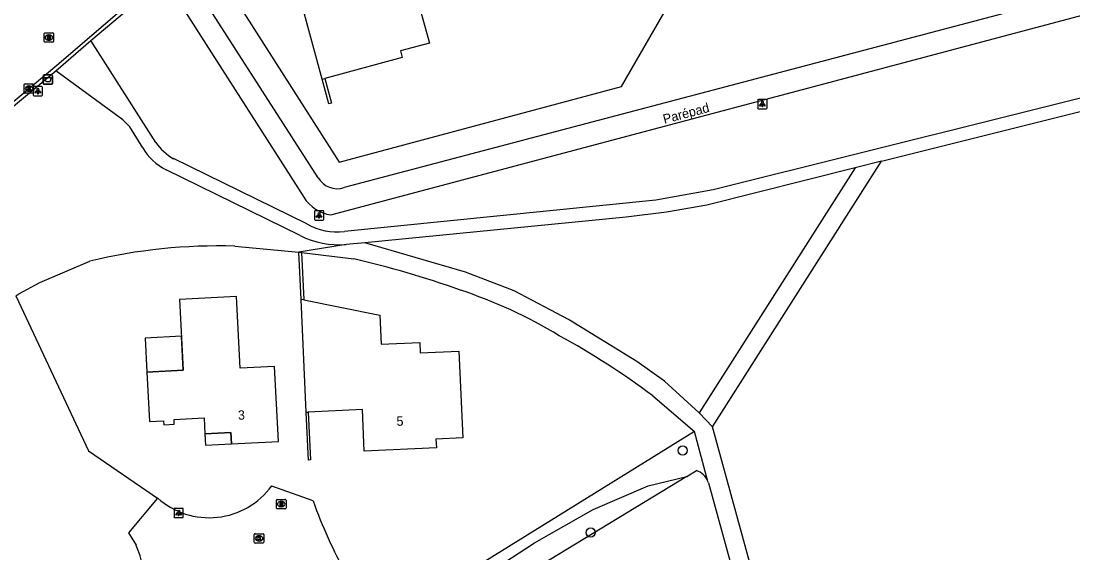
# Model space of a CAD drawing. Extents: x 162157 to 163165, y 378998 to 380775.
# Drawn here: x 162684.3 to 162796.7, y 380157.8 to 380214.6 of the extents above; entities that cross this region are included whole.
import ezdxf

# ---------------------------------------------------------------- set-up
doc = ezdxf.new("R2010")
doc.units = 0
for name, color, linetype in [('IMGEO_Afvalbak', 7, 'Continuous'), ('IMGEO_Boom', 7, 'Continuous'), ('IMGEO_Gemengd_bos', 7, 'Continuous'), ('IMGEO_Grasland_overig', 7, 'Continuous'), ('IMGEO_Groenvoorziening', 7, 'Continuous'), ('IMGEO_Kolk', 7, 'Continuous'), ('IMGEO_Lichtpunt', 7, 'Continuous'), ('IMGEO_Muur', 7, 'Continuous'), ('IMGEO_Naaldbos', 7, 'Continuous'), ('IMGEO_Openbare_ruimte_label', 7, 'Continuous'), ('IMGEO_Pand', 7, 'Continuous'), ('IMGEO_Pand_nummerreeks', 7, 'Continuous'), ('IMGEO_Pand_overbouw', 7, 'Continuous'), ('IMGEO_Rijbaan_lokaal_gesloten', 7, 'Continuous'), ('IMGEO_Rijbaan_lokaal_open', 7, 'Continuous'), ('IMGEO_Rioolput', 7, 'Continuous'), ('IMGEO_Voetpad_halfverhard', 7, 'Continuous'), ('IMGEO_Voetpad_open', 7, 'Continuous')]:
    doc.layers.add(name, color=color, linetype=linetype)

msp = doc.modelspace()

# ---------------------------------------------------------------- linework, layer by layer
at = {"layer": 'IMGEO_Afvalbak'}
for p, q in [((162686.68, 380207.92), (162686.68, 380208.72)), ((162686.68, 380208.72), (162686.68, 380207.92)), ((162686.78, 380208.82), (162687.57, 380208.82)), ((162687.57, 380208.82), (162686.78, 380208.82)), ((162687.67, 380208.72), (162687.67, 380207.92)), ((162687.67, 380207.92), (162687.67, 380208.72)), ((162687.57, 380207.82), (162686.78, 380207.82)), ((162686.78, 380207.82), (162687.57, 380207.82))]:
    msp.add_line(p, q, dxfattribs=at)
msp.add_lwpolyline([(162686.82, 380208.54), (162687.53, 380208.54), (162687.38, 380208.07), (162686.97, 380208.07), (162686.82, 380208.54)], dxfattribs=at)
for centre, start, end in [((162686.78, 380208.72), 90, 180), ((162686.78, 380208.72), 90, 180), ((162687.57, 380208.72), 0, 90), ((162687.57, 380208.72), 360, 90), ((162686.78, 380207.92), 180, 270), ((162686.78, 380207.92), 180, 270), ((162687.57, 380207.92), 270, 0), ((162687.57, 380207.92), 270, 0)]:
    msp.add_arc(centre, 0.1, start, end, dxfattribs=at)
at = {"layer": 'IMGEO_Boom'}
for centre in [(162755.02, 380168.72), (162745.18, 380159.96)]:
    msp.add_circle(centre, 0.489, dxfattribs=at)
at = {"layer": 'IMGEO_Gemengd_bos'}
msp.add_lwpolyline([(162706.23, 380218.45), (162718.29, 380199.51), (162748.49, 380207.59), (162771.73, 380247.86), (162783, 380245.41)], dxfattribs=at)
at = {"layer": 'IMGEO_Grasland_overig'}
msp.add_lwpolyline([(162683.75, 380185.24), (162691.52, 380168.67), (162698.9, 380163.63)], dxfattribs=at)
at = {"layer": 'IMGEO_Groenvoorziening'}
msp.add_lwpolyline([(162755.47, 380165.95), (162726.2, 380148.17)], dxfattribs=at)
at = {"layer": 'IMGEO_Kolk'}
for p, q in [((162684.65, 380206.94), (162684.65, 380207.79)), ((162684.73, 380207.87), (162685.58, 380207.87)), ((162685.14, 380207.64), (162685.17, 380207.64)), ((162685.65, 380207.79), (162685.65, 380206.94)), ((162685.58, 380206.86), (162684.73, 380206.86)), ((162685.16, 380207.09), (162685.14, 380207.09)), ((162709.23, 380158.91), (162709.23, 380159.76)), ((162709.31, 380159.83), (162710.16, 380159.83)), ((162709.72, 380159.61), (162709.75, 380159.61)), ((162710.24, 380159.76), (162710.24, 380158.91)), ((162710.16, 380158.83), (162709.31, 380158.83)), ((162709.74, 380159.05), (162709.72, 380159.05))]:
    msp.add_line(p, q, dxfattribs=at)
for points in [[(162684.65, 380206.94), (162684.65, 380207.79)], [(162684.73, 380207.87), (162685.58, 380207.87)], [(162685.65, 380207.79), (162685.65, 380206.94)], [(162685.58, 380206.86), (162684.73, 380206.86)], [(162684.97, 380207.56), (162685.1, 380207.56), (162685.1, 380207.41), (162685.23, 380207.56), (162685.39, 380207.56), (162685.25, 380207.41), (162685.4, 380207.16), (162685.25, 380207.16), (162685.16, 380207.33), (162685.1, 380207.26), (162685.1, 380207.16), (162684.97, 380207.16), (162684.97, 380207.56)], [(162709.23, 380158.91), (162709.23, 380159.76)], [(162709.31, 380159.83), (162710.16, 380159.83)], [(162709.55, 380159.53), (162709.68, 380159.53), (162709.68, 380159.38), (162709.81, 380159.53), (162709.97, 380159.53), (162709.83, 380159.38), (162709.98, 380159.13), (162709.83, 380159.13), (162709.74, 380159.3), (162709.68, 380159.23), (162709.68, 380159.13), (162709.55, 380159.13), (162709.55, 380159.53)], [(162710.24, 380159.76), (162710.24, 380158.91)], [(162710.16, 380158.83), (162709.31, 380158.83)]]:
    msp.add_lwpolyline(points, dxfattribs=at)
for centre, start, end in [((162684.73, 380207.79), 91.552, 178.448), ((162684.73, 380207.79), 91.552, 178.448), ((162685.58, 380207.79), 1.552, 88.448), ((162685.58, 380207.79), 1.552, 88.448), ((162684.73, 380206.94), 181.552, 268.448), ((162684.73, 380206.94), 181.552, 268.448), ((162685.58, 380206.94), 271.552, 358.448), ((162685.58, 380206.94), 271.552, 358.448), ((162709.31, 380159.76), 91.552, 178.448), ((162709.31, 380159.76), 91.552, 178.448), ((162710.16, 380159.76), 1.552, 88.448), ((162710.16, 380159.76), 1.552, 88.448), ((162709.31, 380158.91), 181.552, 268.448), ((162709.31, 380158.91), 181.552, 268.448), ((162710.16, 380158.91), 271.552, 358.448), ((162710.16, 380158.91), 271.552, 358.448)]:
    msp.add_arc(centre, 0.0765, start, end, dxfattribs=at)
for centre, major_axis, ratio, start_param, end_param in [((162685.14, 380207.36), (-0.387, 0.002), 0.722429, 4.712389, 7.853982), ((162685.16, 380207.36), (-0.39, 0.002), 0.717154, 1.570796, 4.712389), ((162709.72, 380159.33), (-0.387, 0.002), 0.722429, 4.712389, 7.853982), ((162709.75, 380159.33), (-0.39, 0.002), 0.717154, 1.570796, 4.712389)]:
    msp.add_ellipse(centre, major_axis=major_axis, ratio=ratio, start_param=start_param, end_param=end_param, dxfattribs=at)
at = {"layer": 'IMGEO_Lichtpunt'}
for p, q in [((162686.51, 380207.58), (162685.71, 380207.58)), ((162686.51, 380207.58), (162685.71, 380207.58)), ((162685.61, 380207.49), (162685.61, 380206.68)), ((162685.61, 380207.49), (162685.61, 380206.68)), ((162685.71, 380206.59), (162686.51, 380206.59)), ((162685.71, 380206.59), (162686.51, 380206.59)), ((162686.61, 380206.68), (162686.61, 380207.49)), ((162686.61, 380206.68), (162686.61, 380207.49)), ((162763.03, 380206.11), (162763.03, 380205.31)), ((162763.03, 380206.11), (162763.03, 380205.31)), ((162763.93, 380206.21), (162763.12, 380206.21)), ((162763.93, 380206.21), (162763.12, 380206.21)), ((162764.03, 380205.31), (162764.03, 380206.11)), ((162764.03, 380205.31), (162764.03, 380206.11)), ((162763.12, 380205.21), (162763.93, 380205.21)), ((162763.12, 380205.21), (162763.93, 380205.21)), ((162715.65, 380194.23), (162715.65, 380193.42)), ((162715.65, 380194.23), (162715.65, 380193.42)), ((162716.55, 380194.32), (162715.75, 380194.32)), ((162716.55, 380194.32), (162715.75, 380194.32)), ((162716.65, 380193.42), (162716.65, 380194.23)), ((162716.65, 380193.42), (162716.65, 380194.23)), ((162715.75, 380193.32), (162716.55, 380193.32)), ((162715.75, 380193.32), (162716.55, 380193.32)), ((162700.65, 380162.45), (162700.65, 380161.64)), ((162700.65, 380162.45), (162700.65, 380161.64)), ((162701.55, 380162.54), (162700.74, 380162.54)), ((162701.55, 380162.54), (162700.74, 380162.54)), ((162700.74, 380161.55), (162701.55, 380161.55)), ((162700.74, 380161.55), (162701.55, 380161.55)), ((162701.64, 380161.64), (162701.64, 380162.45)), ((162701.64, 380161.64), (162701.64, 380162.45))]:
    msp.add_line(p, q, dxfattribs=at)
for points in [[(162685.99, 380207.15), (162686.03, 380207.13), (162685.84, 380206.86), (162685.8, 380206.89), (162685.99, 380207.15)], [(162686.09, 380207.11), (162686.14, 380207.11), (162686.14, 380206.78), (162686.09, 380206.78), (162686.09, 380207.11)], [(162686.2, 380207.13), (162686.24, 380207.15), (162686.42, 380206.89), (162686.39, 380206.86), (162686.2, 380207.13)], [(162763.4, 380205.78), (162763.44, 380205.75), (162763.26, 380205.49), (162763.22, 380205.51), (162763.4, 380205.78)], [(162763.51, 380205.73), (162763.55, 380205.73), (162763.55, 380205.41), (162763.51, 380205.41), (162763.51, 380205.73)], [(162763.62, 380205.75), (162763.65, 380205.78), (162763.84, 380205.51), (162763.8, 380205.49), (162763.62, 380205.75)], [(162716.03, 380193.89), (162716.06, 380193.86), (162715.88, 380193.6), (162715.84, 380193.63), (162716.03, 380193.89)], [(162716.13, 380193.84), (162716.17, 380193.84), (162716.17, 380193.52), (162716.13, 380193.52), (162716.13, 380193.84)], [(162716.24, 380193.86), (162716.28, 380193.89), (162716.46, 380193.63), (162716.42, 380193.6), (162716.24, 380193.86)], [(162701.02, 380162.11), (162701.06, 380162.09), (162700.87, 380161.82), (162700.83, 380161.85), (162701.02, 380162.11)], [(162701.12, 380162.07), (162701.17, 380162.07), (162701.17, 380161.74), (162701.12, 380161.74), (162701.12, 380162.07)], [(162701.23, 380162.09), (162701.27, 380162.11), (162701.46, 380161.85), (162701.42, 380161.82), (162701.23, 380162.09)]]:
    msp.add_lwpolyline(points, dxfattribs=at)
for centre in [(162686.11, 380207.29), (162763.53, 380205.91), (162716.15, 380194.02), (162701.15, 380162.25)]:
    msp.add_circle(centre, 0.0994, dxfattribs=at)
for centre, start, end in [((162685.71, 380207.49), 90, 180), ((162685.71, 380207.49), 90, 180), ((162686.51, 380207.49), 0, 90), ((162686.51, 380207.49), 0, 90), ((162685.71, 380206.68), 180, 270), ((162685.71, 380206.68), 180, 270), ((162686.51, 380206.68), 270, 0), ((162686.51, 380206.68), 270, 360), ((162763.12, 380206.11), 90, 180), ((162763.12, 380206.11), 90, 180), ((162763.93, 380206.11), 0, 90), ((162763.93, 380206.11), 0, 90), ((162763.12, 380205.31), 180, 270), ((162763.12, 380205.31), 180, 270), ((162763.93, 380205.31), 270, 0), ((162763.93, 380205.31), 270, 360), ((162715.75, 380194.23), 90, 180), ((162715.75, 380194.23), 90, 180), ((162716.55, 380194.23), 0, 90), ((162716.55, 380194.23), 0, 90), ((162715.75, 380193.42), 180, 270), ((162715.75, 380193.42), 180, 270), ((162716.55, 380193.42), 270, 0), ((162716.55, 380193.42), 270, 360), ((162700.74, 380162.45), 90, 180), ((162700.74, 380162.45), 90, 180), ((162700.74, 380161.64), 180, 270), ((162700.74, 380161.64), 180, 270), ((162701.55, 380162.45), 0, 90), ((162701.55, 380162.45), 0, 90), ((162701.55, 380161.64), 270, 0), ((162701.55, 380161.64), 270, 360)]:
    msp.add_arc(centre, 0.0946, start, end, dxfattribs=at)
at = {"layer": 'IMGEO_Muur'}
for points in [[(162716.77, 380208.45), (162717.49, 380205.82), (162717.2, 380205.74), (162716.49, 380208.37)], [(162714, 380189.9), (162714.28, 380189.87)], [(162714.23, 380184.85), (162714, 380189.9)], [(162714.28, 380189.87), (162714.52, 380184.79)], [(162715, 380172.81), (162715.23, 380167.71), (162715.03, 380167.7), (162714.79, 380172.8)]]:
    msp.add_lwpolyline(points, dxfattribs=at)
at = {"layer": 'IMGEO_Naaldbos'}
for points in [[(162707.14, 380190.54), (162714, 380189.9)], [(162683.75, 380185.24), (162684.07, 380185.46), (162686.32, 380186.65), (162691.65, 380188.94)]]:
    msp.add_lwpolyline(points, dxfattribs=at)
msp.add_arc((162705.36, 380131.99), 58.57, 88.2597, 103.5364, dxfattribs=at)
at = {"layer": 'IMGEO_Pand'}
for points in [[(162716.49, 380208.37), (162714.39, 380216.1), (162715.1, 380216.3), (162714.03, 380220.25), (162720.57, 380222.02), (162719.45, 380226.13), (162723.68, 380227.27)], [(162723.9, 380227.33), (162727.13, 380215.42), (162727.08, 380215.4), (162727.94, 380212.22), (162724.86, 380211.39), (162725.05, 380210.69), (162716.77, 380208.45)], [(162716.49, 380208.37), (162716.77, 380208.45)], [(162707.33, 380185.16), (162701.24, 380184.84), (162701.63, 380177.28), (162697.75, 380177.08), (162698.03, 380171.82), (162699.54, 380171.9), (162699.56, 380171.47), (162700.68, 380171.52), (162700.65, 380172.02), (162703.87, 380172.19), (162703.96, 380170.51), (162706.74, 380170.65), (162706.8, 380169.43), (162711.82, 380169.69), (162711.4, 380177.68), (162707.73, 380177.49), (162707.33, 380185.16)], [(162714.79, 380172.8), (162714.23, 380184.85)], [(162714.52, 380184.79), (162714.23, 380184.85)], [(162714.52, 380184.79), (162722.65, 380183.18), (162722.8, 380180.07), (162726.92, 380180.26), (162726.97, 380179.15), (162731.08, 380179.34), (162731.51, 380170.08), (162728.64, 380169.94), (162728.69, 380169.01), (162720.99, 380168.66), (162720.79, 380173.08), (162715, 380172.81)], [(162714.79, 380172.8), (162715, 380172.81)]]:
    msp.add_lwpolyline(points, dxfattribs=at)
at = {"layer": 'IMGEO_Pand_overbouw'}
for points in [[(162697.56, 380180.72), (162697.75, 380177.08), (162701.63, 380177.28), (162701.44, 380180.93)], [(162703.96, 380170.51), (162704.02, 380169.28), (162706.8, 380169.43), (162706.74, 380170.65)]]:
    msp.add_lwpolyline(points, close=True, dxfattribs=at)
at = {"layer": 'IMGEO_Rijbaan_lokaal_gesloten'}
msp.add_lwpolyline([(162699.33, 380219.44), (162688.11, 380209.84), (162656.75, 380183.58)], dxfattribs=at)
at = {"layer": 'IMGEO_Rijbaan_lokaal_open'}
for points in [[(162691.75, 380212.48), (162699.59, 380219.12)], [(162688.01, 380209.27), (162691.75, 380212.48)], [(162655.18, 380181.88), (162688.01, 380209.27)], [(162715.51, 380163.34), (162711.09, 380164.92)], [(162698.9, 380163.63), (162695.78, 380159.94), (162696.6, 380158.59)]]:
    msp.add_lwpolyline(points, dxfattribs=at)
for centre, radius, start, end in [((162704.41, 380169.83), 8.29, 228.3998, 323.7405), ((162766.9, 380181.89), 54.64, 199.8527, 208.8663), ((162688.65, 380154.93), 8.75, 353.8956, 24.664)]:
    msp.add_arc(centre, radius, start, end, dxfattribs=at)
at = {"layer": 'IMGEO_Rioolput'}
for p, q in [((162686.78, 380212.39), (162686.78, 380213.24)), ((162686.85, 380213.31), (162687.7, 380213.31)), ((162687.78, 380213.24), (162687.78, 380212.39)), ((162687.7, 380212.31), (162686.85, 380212.31)), ((162687.26, 380213.09), (162687.29, 380213.09)), ((162687.29, 380212.53), (162687.26, 380212.53)), ((162711.62, 380162.57), (162711.62, 380163.42)), ((162711.69, 380163.49), (162712.54, 380163.49)), ((162712.1, 380163.27), (162712.13, 380163.27)), ((162712.13, 380162.71), (162712.1, 380162.71)), ((162712.62, 380163.42), (162712.62, 380162.57)), ((162712.54, 380162.49), (162711.69, 380162.49))]:
    msp.add_line(p, q, dxfattribs=at)
for points in [[(162686.78, 380212.39), (162686.78, 380213.24)], [(162686.85, 380213.31), (162687.7, 380213.31)], [(162687.78, 380213.24), (162687.78, 380212.39)], [(162687.7, 380212.31), (162686.85, 380212.31)], [(162687.36, 380213.01), (162687.11, 380213.01), (162687.11, 380212.61)], [(162687.11, 380212.61), (162687.24, 380212.61), (162687.24, 380212.78), (162687.25, 380212.78)], [(162687.29, 380212.93), (162687.24, 380212.93), (162687.24, 380212.85)], [(162687.24, 380212.85), (162687.29, 380212.85)], [(162687.29, 380212.75), (162687.37, 380212.61), (162687.5, 380212.61), (162687.44, 380212.74)], [(162711.62, 380162.57), (162711.62, 380163.42)], [(162711.69, 380163.49), (162712.54, 380163.49)], [(162712.21, 380163.19), (162711.95, 380163.19), (162711.95, 380162.79)], [(162711.95, 380162.79), (162712.08, 380162.79), (162712.08, 380162.96), (162712.09, 380162.96)], [(162712.13, 380163.11), (162712.08, 380163.11), (162712.08, 380163.03)], [(162712.08, 380163.03), (162712.13, 380163.03)], [(162712.13, 380162.93), (162712.21, 380162.79), (162712.35, 380162.79), (162712.28, 380162.92)], [(162712.62, 380163.42), (162712.62, 380162.57)], [(162712.54, 380162.49), (162711.69, 380162.49)]]:
    msp.add_lwpolyline(points, dxfattribs=at)
for centre, radius, start, end in [((162686.85, 380213.24), 0.0765, 91.552, 178.448), ((162686.85, 380213.24), 0.0765, 91.552, 178.448), ((162687.7, 380213.24), 0.0765, 1.552, 88.448), ((162687.7, 380213.24), 0.0765, 1.552, 88.448), ((162686.85, 380212.39), 0.0765, 181.552, 268.448), ((162686.85, 380212.39), 0.0765, 181.552, 268.448), ((162687.25, 380212.72), 0.0533, 26.0293, 88.6989), ((162687.3, 380212.84), 0.0964, 77.0061, 93.1865), ((162687.27, 380213.04), 0.19, 274.7715, 282.9687), ((162687.31, 380212.89), 0.0378, 276.6634, 79.6772), ((162687.36, 380212.9), 0.109, 350.3612, 89.416), ((162687.36, 380212.9), 0.112, 277.5842, 350.9817), ((162687.35, 380212.69), 0.108, 29.5134, 73.7905), ((162687.7, 380212.39), 0.0765, 271.552, 358.448), ((162687.7, 380212.39), 0.0765, 271.552, 358.448), ((162711.69, 380163.42), 0.0765, 91.552, 178.448), ((162711.69, 380163.42), 0.0765, 91.552, 178.448), ((162712.09, 380162.9), 0.0533, 26.0293, 88.6989), ((162712.14, 380163.02), 0.0964, 77.0061, 93.1865), ((162712.11, 380163.22), 0.19, 274.7715, 282.9687), ((162712.15, 380163.07), 0.0378, 276.6634, 79.6772), ((162712.2, 380163.08), 0.109, 350.3612, 89.416), ((162712.2, 380163.08), 0.112, 277.5842, 350.9817), ((162712.19, 380162.87), 0.108, 29.5134, 73.7905), ((162712.54, 380163.42), 0.0765, 1.552, 88.448), ((162712.54, 380163.42), 0.0765, 1.552, 88.448), ((162711.69, 380162.57), 0.0765, 181.552, 268.448), ((162711.69, 380162.57), 0.0765, 181.552, 268.448), ((162712.54, 380162.57), 0.0765, 271.552, 358.448), ((162712.54, 380162.57), 0.0765, 271.552, 358.448)]:
    msp.add_arc(centre, radius, start, end, dxfattribs=at)
for centre, major_axis, ratio, start_param, end_param in [((162687.26, 380212.81), (-0.387, 0.002), 0.722429, 4.712389, 7.853982), ((162687.29, 380212.81), (-0.39, 0.002), 0.717154, 1.570796, 4.712389), ((162712.1, 380162.99), (-0.387, 0.002), 0.722429, 4.712389, 7.853982), ((162712.13, 380162.99), (-0.39, 0.002), 0.717154, 1.570796, 4.712389)]:
    msp.add_ellipse(centre, major_axis=major_axis, ratio=ratio, start_param=start_param, end_param=end_param, dxfattribs=at)
at = {"layer": 'IMGEO_Voetpad_halfverhard'}
for points in [[(162698.7, 380201.61), (162691.75, 380212.48)], [(162697.31, 380201.05), (162695.93, 380203.29), (162695.18, 380204.02), (162688.01, 380209.27)], [(162805.25, 380208.27), (162758.28, 380196.55), (162752.14, 380195.44), (162718.86, 380192.09)], [(162776.26, 380199.6), (162805.6, 380206.95)], [(162714.86, 380192.91), (162700.58, 380199.88)], [(162714.12, 380191.67), (162699.81, 380198.7)], [(162773.43, 380198.89), (162757.58, 380194.92), (162753.29, 380194.17), (162748.96, 380193.64), (162721.06, 380190.9)], [(162773.43, 380198.89), (162756.79, 380172.74)], [(162758.21, 380171.26), (162776.26, 380199.6)], [(162776.26, 380199.6), (162773.43, 380198.89)], [(162719.04, 380190.71), (162714, 380189.9)], [(162721.06, 380190.9), (162719.04, 380190.71)], [(162756.79, 380172.74), (162753.06, 380176.11), (162750.13, 380178.22), (162742.81, 380182.7), (162737.02, 380185.75), (162731.8, 380187.77), (162721.06, 380190.9)], [(162714.28, 380189.87), (162719.86, 380189.17)], [(162751.83, 380174.54), (162756.28, 380170.74)], [(162756.79, 380172.74), (162758.21, 380171.26)], [(162756.28, 380170.74), (162732.09, 380155.77)], [(162757.71, 380165.41), (162756.28, 380170.74)], [(162779.59, 380093.44), (162758.21, 380171.26)], [(162755.47, 380165.95), (162756.49, 380166.57)], [(162726.2, 380148.17), (162726.01, 380148.42), (162726, 380149.21), (162729.26, 380152.13), (162731.9, 380154.14), (162739.16, 380158.85), (162745.43, 380162.43), (162751.31, 380164.93), (162755.47, 380165.95)], [(162757.76, 380165.25), (162777.59, 380093.17)]]:
    msp.add_lwpolyline(points, dxfattribs=at)
for centre, radius, start, end in [((162702.36, 380203.92), 5.81, 209.6526, 243.9847), ((162703.74, 380205.2), 6.19, 215.547, 239.3439), ((162718.09, 380198.5), 6.45, 239.9123, 276.8132), ((162718.34, 380200.15), 9.47, 243.5649, 274.2415), ((162697.97, 380092.91), 98.72, 70.3522, 77.1858), ((162715.04, 380136.87), 51.59, 58.721, 71.7894), ((162703.37, 380110.12), 80.61, 53.0519, 61.5113), ((162755.88, 380164.72), 1.95, 20.6804, 71.6854), ((162755.78, 380164.68), 2.06, 16.1883, 20.6816)]:
    msp.add_arc(centre, radius, start, end, dxfattribs=at)
at = {"layer": 'IMGEO_Voetpad_open'}
for points in [[(162699.59, 380219.12), (162714.53, 380195.76)], [(162802.35, 380218.82), (162791.24, 380215.89), (162718.82, 380196.79)], [(162717.42, 380193.88), (162802.93, 380216.6)], [(162716.07, 380197.83), (162704.48, 380215.83)]]:
    msp.add_lwpolyline(points, dxfattribs=at)
for centre, radius, start, end in [((162718.1, 380199.04), 2.37, 210.8424, 287.7586), ((162718.04, 380198), 4.17, 212.5408, 261.47)]:
    msp.add_arc(centre, radius, start, end, dxfattribs=at)

# ---------------------------------------------------------------- texts
at = {"layer": 'IMGEO_Openbare_ruimte_label'}
msp.add_text('Parépad', height=1, rotation=14.8982, dxfattribs=at).set_placement((162753.06, 380203.59))
at = {"layer": 'IMGEO_Pand_nummerreeks'}
for s, rotation, p in [('3', 3.0023, (162707.51, 380171.99)), ('5', 2.6559, (162724.45, 380171.34))]:
    msp.add_text(s, height=1, rotation=rotation, dxfattribs=at).set_placement(p)

doc.saveas('drawing.dxf')
